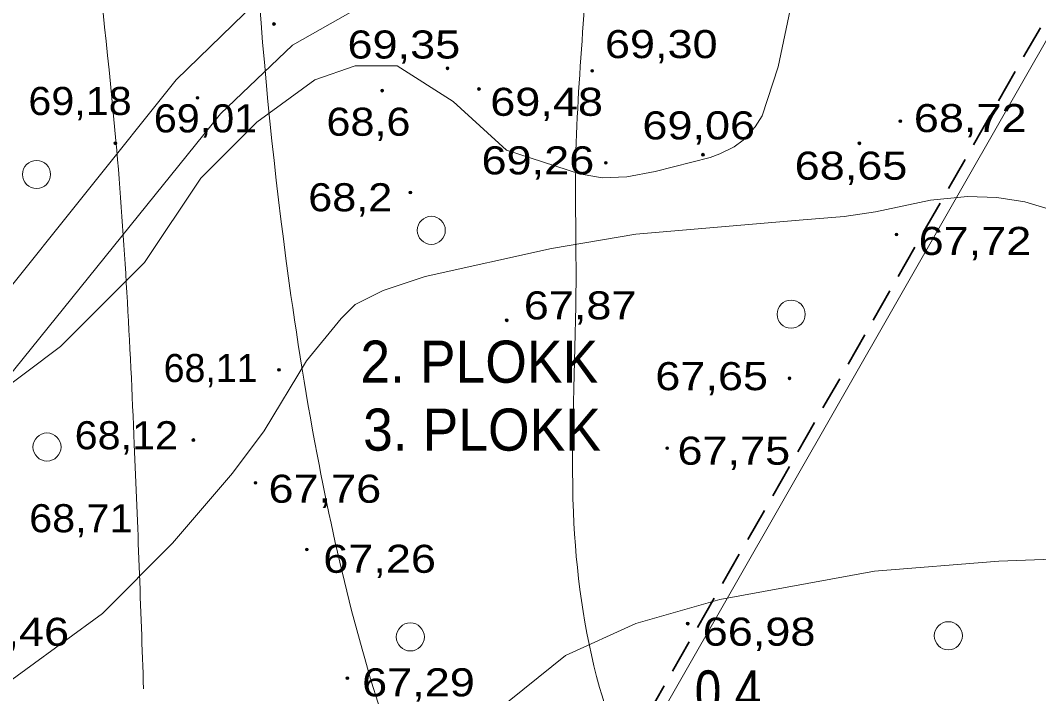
# Model space of a CAD drawing. Extents: x 628176 to 629009, y 6439913 to 6440496.
# Drawn here: x 628361.2 to 628433.7, y 6440288.3 to 6440336.2 of the extents above; entities that cross this region are included whole.
import ezdxf
from ezdxf.enums import TextEntityAlignment as Align

# ---------------------------------------------------------------- set-up
doc = ezdxf.new("R2010")
doc.units = 0
doc.header["$LTSCALE"] = 0.8
doc.linetypes.add('MEDIUM_DASHED', pattern=[4.5, 3, -1.5])
for name, color, linetype, lineweight in [('1', 7, 'Continuous', 13), ('11', 7, 'Continuous', 13), ('12', 7, 'Continuous', 13), ('16', 7, 'Continuous', 13), ('21', 7, 'MEDIUM_DASHED', 35), ('3', 7, 'Continuous', 13)]:
    doc.layers.add(name, color=color, linetype=linetype, lineweight=lineweight)

msp = doc.modelspace()

# ---------------------------------------------------------------- hatches: boundary and pattern name
at = {"layer": '1'}
for points in [[(628379.3184, 6440335.9805, 1), (628379.1184, 6440335.9805, 1)], [(628391.6854, 6440332.8269, 1), (628391.4854, 6440332.8269, 1)], [(628401.9942, 6440332.6403, 1), (628401.7942, 6440332.6403, 1)], [(628387.0317, 6440331.2348, 1), (628386.8317, 6440331.2348, 1)], [(628393.9262, 6440331.3511, 1), (628393.7262, 6440331.3511, 1)], [(628373.8753, 6440330.7178, 1), (628373.6753, 6440330.7178, 1)], [(628423.9461, 6440329.0651, 1), (628423.7461, 6440329.0651, 1)], [(628368.0185, 6440327.4836, 1), (628367.8185, 6440327.4836, 1)], [(628421.0299, 6440327.4858, 1), (628420.8299, 6440327.4858, 1)], [(628409.8844, 6440326.6719, 1), (628409.6844, 6440326.6719, 1)], [(628402.9648, 6440326.089, 1), (628402.7648, 6440326.089, 1)], [(628389.041, 6440323.975, 1), (628388.841, 6440323.975, 1)], [(628423.6815, 6440320.9905, 1), (628423.4815, 6440320.9905, 1)], [(628395.902, 6440314.8792, 1), (628395.702, 6440314.8792, 1)], [(628379.6745, 6440311.3465, 1), (628379.4745, 6440311.3465, 1)], [(628416.0499, 6440310.7462, 1), (628415.8499, 6440310.7462, 1)], [(628373.5779, 6440306.3473, 1), (628373.3779, 6440306.3473, 1)], [(628407.3314, 6440305.765, 1), (628407.1314, 6440305.765, 1)], [(628377.9998, 6440303.2956, 1), (628377.7998, 6440303.2956, 1)], [(628381.6616, 6440298.5462, 1), (628381.4616, 6440298.5462, 1)], [(628408.8002, 6440293.2699, 1), (628408.6002, 6440293.2699, 1)], [(628384.5485, 6440289.3821, 1), (628384.3485, 6440289.3821, 1)]]:
    msp.add_hatch(color=256, dxfattribs=at).paths.add_polyline_path(points)

# ---------------------------------------------------------------- linework, layer by layer
for p, q in [((628398.05, 6440344.39), (628380.54, 6440334.48)), ((628372.24, 6440332), (628377.9, 6440337.48)), ((628375.42, 6440329.58), (628380.54, 6440334.48)), ((628353.99, 6440309.2), (628372.24, 6440332)), ((628357.63, 6440307.56), (628375.42, 6440329.58))]:
    msp.add_line(p, q, dxfattribs=at)
for centre, radius in [((628379.2184, 6440335.9805), 0.1), ((628391.5854, 6440332.8269), 0.1), ((628401.8942, 6440332.6403), 0.1), ((628386.9317, 6440331.2348), 0.1), ((628393.8262, 6440331.3511), 0.1), ((628373.7753, 6440330.7178), 0.1), ((628423.8461, 6440329.0651), 0.1), ((628367.9185, 6440327.4836), 0.1), ((628420.9299, 6440327.4858), 0.1), ((628409.7844, 6440326.6719), 0.1), ((628362.3012, 6440325.2662), 1), ((628402.8648, 6440326.089), 0.1), ((628388.941, 6440323.975), 0.1), ((628390.4291, 6440321.2835), 1), ((628423.5815, 6440320.9905), 0.1), ((628416.0678, 6440315.3094), 1), ((628395.802, 6440314.8792), 0.1), ((628379.5745, 6440311.3465), 0.1), ((628415.9499, 6440310.7462), 0.1), ((628363.048, 6440305.8505), 1), ((628373.4779, 6440306.3473), 0.1), ((628407.2314, 6440305.765), 0.1), ((628377.8998, 6440303.2956), 0.1), ((628381.5616, 6440298.5462), 0.1), ((628408.7002, 6440293.2699), 0.1), ((628427.2692, 6440292.4088), 1), ((628388.9356, 6440292.3245), 1), ((628384.4485, 6440289.3821), 0.1)]:
    msp.add_circle(centre, radius, dxfattribs=at)
at = {"layer": '11'}
msp.add_lwpolyline([(628479.31, 6440413.61), (628403.76, 6440281.52), (628439.01, 6440242.62), (628472.21, 6440157.1)], dxfattribs=at)
at = {"layer": '16'}
for points in [[(628417.51, 6440405.33), (628413.04, 6440391.73), (628407.64, 6440376.09), (628405.21, 6440367.15), (628402.23, 6440348.89), (628401.3, 6440336.6), (628400.74, 6440326.92), (628400.74, 6440316.86), (628400.56, 6440301.21), (628402.42, 6440288.73), (628405.96, 6440280.54), (628414.34, 6440271.97), (628424.59, 6440263.4), (628430.76, 6440257.95)], [(628377.28, 6440389.13), (628377.09, 6440364.17), (628380.07, 6440319.28), (628382.3, 6440305.31), (628388.08, 6440283.33), (628396.46, 6440266.57), (628400.19, 6440262.1), (628404.68, 6440258.52)], [(628364.8, 6440366.03), (628364.98, 6440360.07), (628367.96, 6440327.66), (628369.27, 6440306.05), (628369.93, 6440288.62)]]:
    msp.add_spline(points, degree=3, dxfattribs=at)
at = {"layer": '21'}
msp.add_lwpolyline([(628476.73, 6440410.71), (628402.77, 6440281.42), (628438.32, 6440242.19), (628470.2, 6440160.05)], dxfattribs=at)
at = {"layer": '3'}
for p, q in [((628401, 6440325.32), (628402.61, 6440325.03)), ((628402.61, 6440325.03), (628404.36, 6440325.1)), ((628422.08, 6440322.6), (628419.85, 6440322.28)), ((628405, 6440321), (628416.63, 6440322)), ((628416.63, 6440322), (628419.85, 6440322.28)), ((628405, 6440321), (628399, 6440320)), ((628444.47, 6440298.24), (628430.86, 6440297.72)), ((628405, 6440293.27), (628411, 6440295)), ((628400, 6440291), (628405, 6440293.27))]:
    msp.add_line(p, q, dxfattribs=at)
for points in [[(628421.56, 6440346.2), (628419.39, 6440344), (628418, 6440342), (628417, 6440340), (628416, 6440337), (628415.14, 6440332.94), (628414, 6440329.43)], [(628401, 6440325.32), (628395.8, 6440327), (628392, 6440330.46), (628388, 6440333), (628385, 6440333), (628382.14, 6440332), (628378, 6440329), (628374, 6440325)], [(628404.36, 6440325.1), (628406.38, 6440325.48), (628410.29, 6440326.48), (628411, 6440326.74), (628412, 6440327.23), (628412.66, 6440327.7), (628413.51, 6440328.65), (628414, 6440329.43)], [(628359, 6440309.25), (628364, 6440313), (628370, 6440319), (628374, 6440325)], [(628447.49, 6440314), (628445.68, 6440315), (628444.27, 6440316), (628441.97, 6440318), (628440.06, 6440319.6), (628438.15, 6440321), (628436.46, 6440322), (628435, 6440322.62), (628432.73, 6440323.31), (628430.72, 6440323.63), (628428.63, 6440323.7), (628426, 6440323.44), (628422.08, 6440322.6)], [(628381.54, 6440312), (628384, 6440315), (628385, 6440316), (628387, 6440317), (628390, 6440318), (628399, 6440320)], [(628371.31, 6440273.83), (628370, 6440276), (628369, 6440276), (628367, 6440275), (628365, 6440272), (628361, 6440268), (628357, 6440267), (628351.41, 6440267), (628350, 6440268), (628349, 6440271), (628350, 6440278), (628352, 6440283), (628354, 6440285), (628358.78, 6440288), (628367, 6440294), (628372, 6440299), (628376.27, 6440304), (628378.53, 6440307), (628381.54, 6440312)], [(628411, 6440295), (628422, 6440297), (628430.86, 6440297.72)], [(628351.82, 6440241.56), (628361, 6440247.17), (628368, 6440249), (628373.51, 6440249), (628378, 6440248), (628381, 6440248), (628383, 6440250), (628385, 6440255), (628389, 6440258), (628395, 6440263), (628394.03, 6440267), (628390, 6440273), (628389, 6440277), (628390, 6440281), (628395, 6440287), (628400, 6440291)]]:
    msp.add_lwpolyline(points, dxfattribs=at)

# ---------------------------------------------------------------- texts
at = {"layer": '1'}
for s, width, p in [('69,35', 1.2, (628384.46, 6440333.52)), ('69,30', 1.2, (628402.8, 6440333.55)), ('69,18', 1.1, (628361.72, 6440329.5)), ('69,48', 1.2, (628394.63, 6440329.44)), ('69,01', 1.1, (628370.66, 6440328.26)), ('68,6', 1.15, (628382.96, 6440328.02)), ('69,06', 1.2, (628405.47, 6440327.76)), ('68,72', 1.2, (628424.81, 6440328.28)), ('69,26', 1.2, (628394.01, 6440325.27)), ('68,65', 1.2, (628416.32, 6440324.89)), ('68,2', 1.15, (628381.66, 6440322.64)), ('67,72', 1.2, (628425.15, 6440319.53)), ('67,87', 1.2, (628397.02, 6440314.94)), ('67,65', 1.2, (628406.39, 6440309.9)), ('68,12', 1.1, (628365.02, 6440305.69)), ('67,75', 1.2, (628407.97, 6440304.59)), ('67,76', 1.2, (628378.83, 6440301.88)), ('68,71', 1.1, (628361.78, 6440299.78)), ('67,26', 1.2, (628382.73, 6440296.89)), ('68,46', 1.2, (628356.59, 6440291.69)), ('66,98', 1.2, (628409.77, 6440291.7)), ('67,29', 1.2, (628385.5, 6440288.09))]:
    msp.add_text(s, height=2, dxfattribs=dict(at, width=width)).set_placement(p)
msp.add_text('68,11', height=2, dxfattribs=at).set_placement((628371.36, 6440310.48))
at = {"layer": '12', "width": 0.85}
msp.add_text('0,4', height=3, dxfattribs=at).set_placement((628411.57, 6440286.94), align=Align.CENTER)
at = {"layer": '21', "width": 0.95}
for s, p in [('2. PLOKK', (628393.85, 6440310.43)), ('3. PLOKK', (628394.045, 6440305.59))]:
    msp.add_text(s, height=3, dxfattribs=at).set_placement(p, align=Align.CENTER)

doc.saveas('drawing.dxf')
